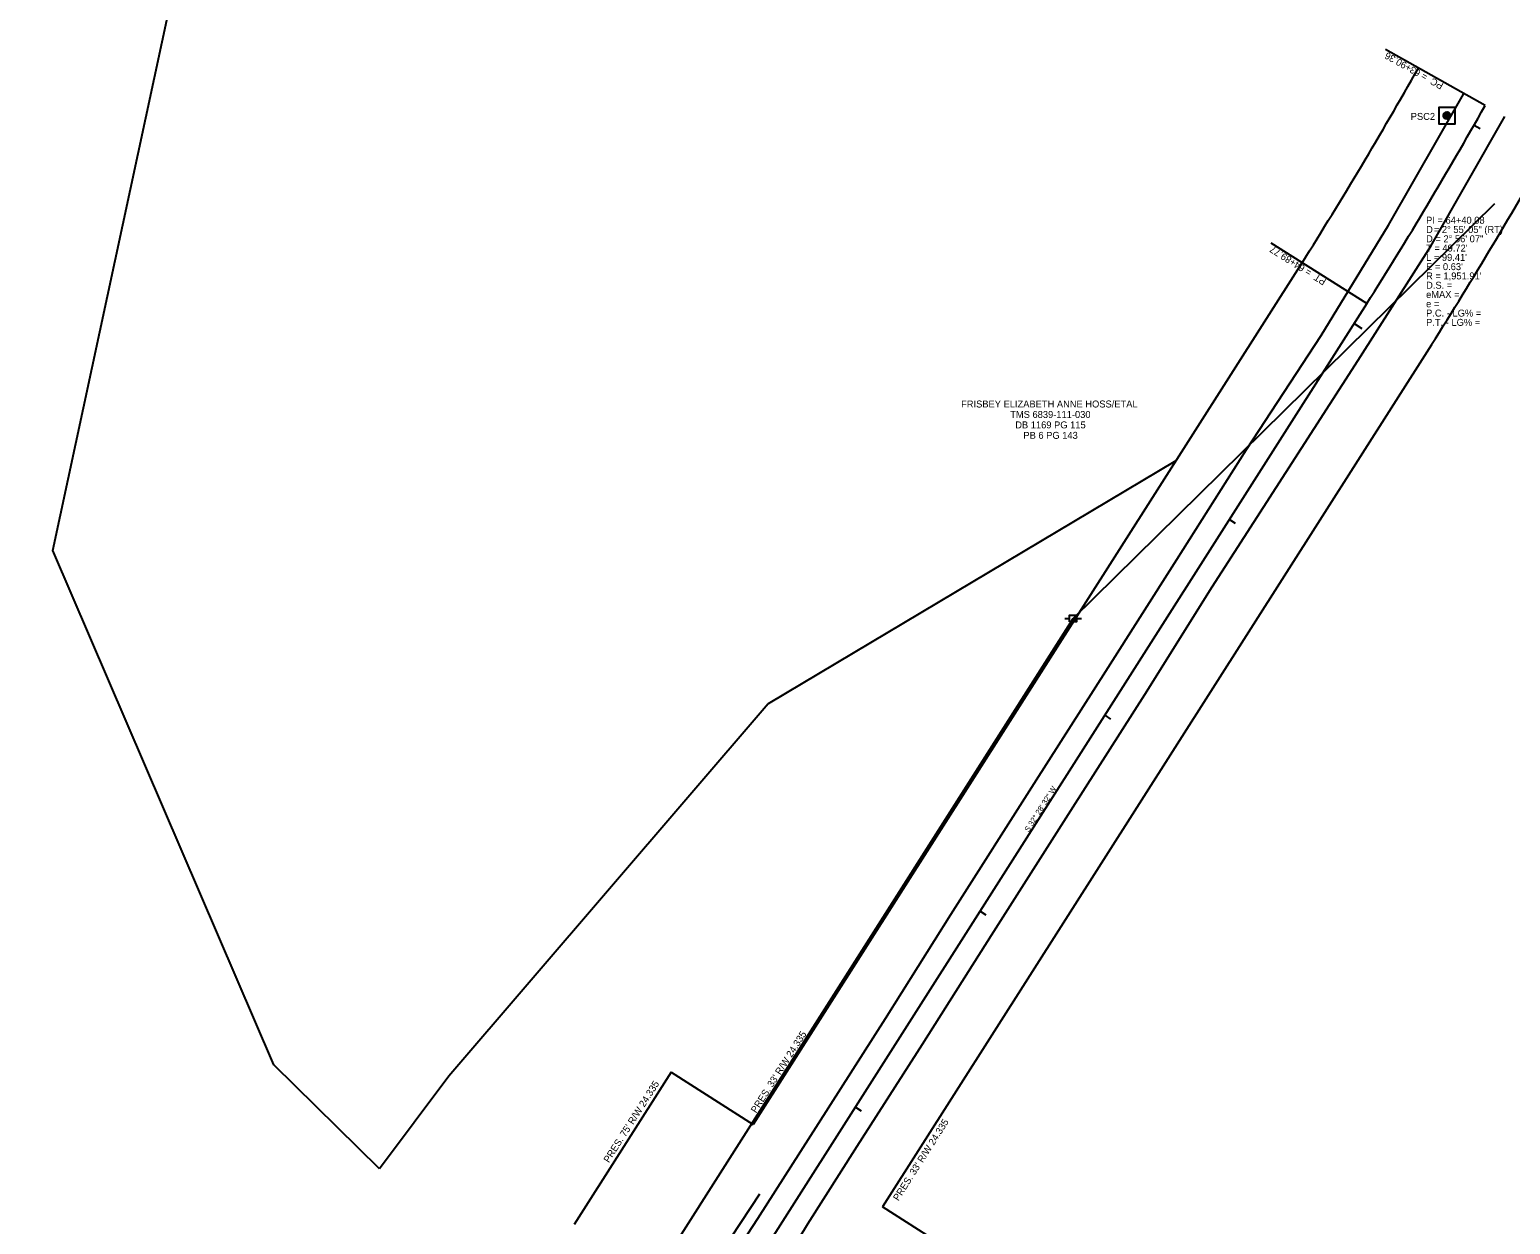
# Model space of a CAD drawing. Extents: x 1628604 to 1635417, y 886385 to 890338.
# Drawn here: x 1631014 to 1631651, y 888509 to 889024 of the extents above; entities that cross this region are included whole.
import ezdxf

# ---------------------------------------------------------------- set-up
doc = ezdxf.new("R2010")
doc.units = 0
for name, color, linetype in [('RD_EX_DV_Prop', 7, 'Continuous'), ('RD_EX_DV_TX_Prop', 7, 'Continuous'), ('RD_EX_GuardRail', 7, 'Continuous'), ('RD_EX_Road', 7, 'Continuous'), ('RD_EX_RW', 7, 'Continuous'), ('RD_EX_RW_TX', 7, 'Continuous'), ('RD_EX_SU_Pole', 7, 'Continuous'), ('RD_EX_UT', 7, 'Continuous'), ('RD_HC_Cl', 7, 'Continuous'), ('RD_HC_Data', 7, 'Continuous'), ('RD_HC_Data_Tic', 7, 'Continuous'), ('RD_HC_Survey', 7, 'Continuous'), ('RD_HC_Survey_txCode', 7, 'Continuous')]:
    doc.layers.add(name, color=color, linetype=linetype)

msp = doc.modelspace()

# ---------------------------------------------------------------- linework, layer by layer
at = {"layer": 'RD_EX_DV_Prop'}
for p, q in [((1631507.28, 888837.92), (1631331.61, 888733.21)), ((1631331.61, 888733.21), (1631194.18, 888572.83)), ((1631194.18, 888572.83), (1631164.23, 888532.87))]:
    msp.add_line(p, q, dxfattribs=at)
msp.add_lwpolyline([(1631164.23, 888532.87), (1631118.71, 888577.64), (1631023.51, 888799.16), (1631080.63, 889064.56), (1630941.57, 889539.42), (1630839.26, 889644.3), (1630710, 889675.24), (1630632.16, 889815.73), (1630615.77, 889972.38), (1630628.75, 890217.75), (1630347.03, 889910.61), (1630126.69, 889847.68)], dxfattribs=at)
at = {"layer": 'RD_EX_GuardRail'}
msp.add_lwpolyline([(1631237.99, 888370.31), (1631264.09, 888412.85), (1631299.43, 888478.7), (1631328.07, 888522.09)], dxfattribs=at)
at = {"layer": 'RD_EX_Road'}
for points in [[(1631304.13, 888476.05), (1631327.2, 888511.47), (1631353.37, 888552.4), (1631382.17, 888597.67), (1631410.29, 888642.38), (1631447.25, 888700.39), (1631477.06, 888747.25), (1631507.66, 888795.35), (1631537.64, 888842.77), (1631569.84, 888891.79), (1631598.86, 888939.42), (1631631.08, 888995.78)], [(1631322.12, 888465.29), (1631348.79, 888509.12), (1631369.96, 888542.66), (1631398.1, 888586.56), (1631427.83, 888633.53), (1631463.03, 888688.76), (1631493.9, 888737.13), (1631522.93, 888783.61), (1631554.59, 888832.78), (1631585.79, 888881.16), (1631616.98, 888930.37), (1631648.97, 888986.19)]]:
    msp.add_lwpolyline(points, dxfattribs=at)
at = {"layer": 'RD_EX_RW'}
for p, q in [((1631561.61, 888923.28), (1631325.24, 888551.9)), ((1631617.29, 888887.85), (1631380.92, 888516.46)), ((1631289.81, 888574.45), (1631248.1, 888508.93)), ((1631289.81, 888574.45), (1631325.24, 888551.9)), ((1631416.35, 888493.91), (1631380.92, 888516.46))]:
    msp.add_line(p, q, dxfattribs=at)
for radius in [1918.91, 1984.91]:
    msp.add_arc((1629939.74, 889948.82), radius, 327.69129, 330.60947, dxfattribs=at)
at = {"layer": 'RD_EX_SU_Pole'}
for p, q in [((1631459.41, 888769.89), (1631461.47, 888769.89)), ((1631462.97, 888769.93), (1631462.97, 888769.93)), ((1631464.47, 888769.89), (1631466.61, 888769.89))]:
    msp.add_line(p, q, dxfattribs=at)
msp.add_lwpolyline([(1631461.47, 888768.43), (1631461.47, 888771.43), (1631464.47, 888771.43), (1631464.47, 888768.43)], close=True, dxfattribs=at)
at = {"layer": 'RD_EX_UT'}
msp.add_lwpolyline([(1631102.27, 888108.59), (1631233.31, 888408.75), (1631462.97, 888769.93), (1631644.65, 888948.73)], dxfattribs=at)
at = {"layer": 'RD_HC_Cl'}
msp.add_line((1631589.45, 888905.57), (1631311.37, 888468.65), dxfattribs=at)
msp.add_arc((1629939.74, 889948.82), 1951.91, 327.69129, 330.60947, dxfattribs=at)
at = {"layer": 'RD_HC_Data'}
for p, q in [((1631640.43, 888990.91), (1631597.5, 889015.09)), ((1631589.45, 888905.57), (1631548.22, 888931.64))]:
    msp.add_line(p, q, dxfattribs=at)
at = {"layer": 'RD_HC_Data_Tic'}
for p, q in [((1631635.68, 888982.52), (1631638.28, 888981.03)), ((1631583.96, 888896.94), (1631587.34, 888894.79)), ((1631530.27, 888812.58), (1631532.8, 888810.97)), ((1631476.58, 888728.22), (1631479.11, 888726.6)), ((1631422.88, 888643.85), (1631425.41, 888642.24)), ((1631369.19, 888559.49), (1631371.72, 888557.88))]:
    msp.add_line(p, q, dxfattribs=at)
at = {"layer": 'RD_HC_Survey'}
for p, q in [((1631622.49, 888986.22), (1631622.49, 888986.94)), ((1631622.54, 888986.05), (1631622.54, 888987.11)), ((1631622.59, 888985.93), (1631622.59, 888987.23)), ((1631622.64, 888985.83), (1631622.64, 888987.33)), ((1631622.69, 888985.74), (1631622.69, 888987.41)), ((1631622.74, 888985.67), (1631622.74, 888987.49)), ((1631622.79, 888985.6), (1631622.79, 888987.55)), ((1631622.84, 888985.55), (1631622.84, 888987.61)), ((1631622.89, 888985.49), (1631622.89, 888987.66)), ((1631622.94, 888985.44), (1631622.94, 888987.71)), ((1631622.99, 888985.4), (1631622.99, 888987.76)), ((1631623.04, 888985.36), (1631623.04, 888987.8)), ((1631623.09, 888985.32), (1631623.09, 888987.84)), ((1631623.14, 888985.28), (1631623.14, 888987.87)), ((1631623.19, 888985.25), (1631623.19, 888987.9)), ((1631623.24, 888985.22), (1631623.24, 888987.93)), ((1631623.29, 888985.2), (1631623.29, 888987.96)), ((1631623.34, 888985.17), (1631623.34, 888987.98)), ((1631623.39, 888985.15), (1631623.39, 888988.01)), ((1631623.44, 888985.13), (1631623.44, 888988.03)), ((1631623.49, 888985.11), (1631623.49, 888988.05)), ((1631623.54, 888985.09), (1631623.54, 888988.06)), ((1631623.59, 888985.08), (1631623.59, 888988.08)), ((1631623.64, 888985.07), (1631623.64, 888988.09)), ((1631623.69, 888985.06), (1631623.69, 888988.1)), ((1631623.74, 888985.05), (1631623.74, 888988.11)), ((1631623.79, 888985.04), (1631623.79, 888988.12)), ((1631623.84, 888985.03), (1631623.84, 888988.12)), ((1631623.89, 888985.03), (1631623.89, 888988.13)), ((1631623.94, 888985.02), (1631623.94, 888988.13)), ((1631623.99, 888985.02), (1631623.99, 888988.13)), ((1631624.04, 888985.02), (1631624.04, 888988.13)), ((1631624.09, 888985.03), (1631624.09, 888988.13)), ((1631624.14, 888985.03), (1631624.14, 888988.13)), ((1631624.19, 888985.03), (1631624.19, 888988.12)), ((1631624.24, 888985.04), (1631624.24, 888988.11)), ((1631624.29, 888985.05), (1631624.29, 888988.11)), ((1631624.34, 888985.06), (1631624.34, 888988.1)), ((1631624.39, 888985.07), (1631624.39, 888988.08)), ((1631624.44, 888985.09), (1631624.44, 888988.07)), ((1631624.49, 888985.1), (1631624.49, 888988.05)), ((1631624.54, 888985.12), (1631624.54, 888988.04)), ((1631624.59, 888985.14), (1631624.59, 888988.02)), ((1631624.64, 888985.16), (1631624.64, 888988)), ((1631624.69, 888985.18), (1631624.69, 888987.97)), ((1631624.74, 888985.21), (1631624.74, 888987.95)), ((1631624.79, 888985.24), (1631624.79, 888987.92)), ((1631624.84, 888985.27), (1631624.84, 888987.89)), ((1631624.89, 888985.3), (1631624.89, 888987.85)), ((1631624.94, 888985.34), (1631624.94, 888987.82)), ((1631624.99, 888985.38), (1631624.99, 888987.78)), ((1631625.04, 888985.42), (1631625.04, 888987.74)), ((1631625.09, 888985.47), (1631625.09, 888987.69)), ((1631625.14, 888985.52), (1631625.14, 888987.64)), ((1631625.19, 888985.58), (1631625.19, 888987.58)), ((1631625.24, 888985.64), (1631625.24, 888987.52)), ((1631625.29, 888985.71), (1631625.29, 888987.45)), ((1631625.34, 888985.79), (1631625.34, 888987.37)), ((1631625.39, 888985.88), (1631625.39, 888987.28)), ((1631625.44, 888985.99), (1631625.44, 888987.17)), ((1631625.49, 888986.13), (1631625.49, 888987.03)), ((1631625.54, 888986.35), (1631625.54, 888986.8))]:
    msp.add_line(p, q, dxfattribs=at)
msp.add_lwpolyline([(1631627.53, 888990.11), (1631620.46, 888990.11), (1631620.46, 888983.04), (1631627.53, 888983.04)], close=True, dxfattribs=at)
msp.add_circle((1631624, 888986.58), 1.55, dxfattribs=at)

# ---------------------------------------------------------------- texts
at = {"layer": 'RD_EX_DV_TX_Prop'}
for s, p in [('FRISBEY ELIZABETH ANNE HOSS/ETAL', (1631414.74, 888860.83)), ('TMS 6839-111-030', (1631435.91, 888856.33)), ('DB 1169 PG 115', (1631438.06, 888851.83)), ('PB 6 PG 143', (1631441.57, 888847.33))]:
    msp.add_text(s, height=3, dxfattribs=at).set_placement(p)
at = {"layer": 'RD_EX_RW_TX'}
for s, p in [("PRES. 33' R/W 24.335", (1631326.48, 888556.64)), ("PRES. 75' R/W 24.335", (1631263.06, 888535.23)), ("PRES. 33' R/W 24.335", (1631387.74, 888518.8))]:
    msp.add_text(s, height=3, rotation=57.5244, dxfattribs=at).set_placement(p)
at = {"layer": 'RD_HC_Data'}
for s, height, rotation, p in [('PC  = 63+90.36', 3, 150.60947, (1631622.76, 889000.28)), ('PT  = 64+89.77', 3, 147.69129, (1631572.28, 888915.83)), ('S 32%%d 28\' 32" W', 2.4, 57.5244, (1631443.85, 888677.73))]:
    msp.add_text(s, height=height, rotation=rotation, dxfattribs=at).set_placement(p)
for s, p in [('PI = 64+40.08', (1631615, 888940)), ('D', (1631615, 888936)), ('   = 2%%d 55\' 05" (RT)', (1631615, 888936)), ("T = 49.72'", (1631615, 888928)), ('D = 2%%d 56\' 07"', (1631615, 888932)), ("L = 99.41'", (1631615, 888924)), ("E = 0.63'", (1631615, 888920)), ("R = 1,951.91'", (1631615, 888916)), ('eMAX = ', (1631615, 888908)), ('D.S. = ', (1631615, 888912)), ('e = ', (1631615, 888904)), ('P.C. - LG% = ', (1631615, 888900)), ('P.T. - LG% = ', (1631615, 888896))]:
    msp.add_text(s, height=3, dxfattribs=at).set_placement(p)
at = {"layer": 'RD_HC_Survey_txCode'}
msp.add_text('PSC2', height=3, dxfattribs=at).set_placement((1631608.38, 888984.72))

doc.saveas('drawing.dxf')
